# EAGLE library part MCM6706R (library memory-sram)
MEMORY
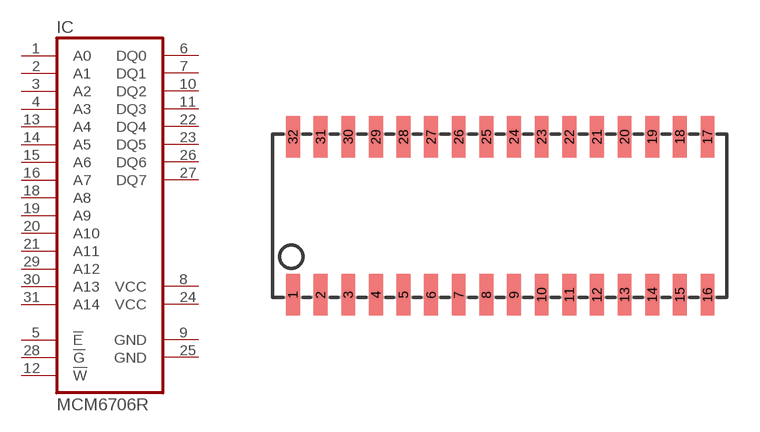
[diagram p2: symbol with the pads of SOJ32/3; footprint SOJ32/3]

Designator prefix IC

## MCM6706R  [SOJ32/3]
1  A0  in
2  A1  in
3  A2  in
4  A3  in
5  !E  in
6  DQ0
7  DQ1
8  VCC  pwr
9  GND  pwr
10  DQ2
11  DQ3
12  !W  in
13  A4  in
14  A5  in
15  A6  in
16  A7  in
18  A8  in
19  A9  in
20  A10  in
21  A11  in
22  DQ4
23  DQ5
24  VCC  pwr
25  GND  pwr
26  DQ6
27  DQ7
28  !G  in
29  A12  in
30  A13  in
31  A14  in

## Footprint SOJ32/3 (pad centres in mm)
Small Outline J-Bend
smd 0.635 x 1.905: 1 -9.525,-3.632; 2 -8.255,-3.632; 3 -6.985,-3.632; 4 -5.715,-3.632; 5 -4.445,-3.632; 6 -3.175,-3.632; 7 -1.905,-3.632; 8 -0.635,-3.632; 9 0.635,-3.632; 10 1.905,-3.632; 11 3.175,-3.632; 12 4.445,-3.632; 13 5.715,-3.632; 14 6.985,-3.632; 15 8.255,-3.632; 16 9.525,-3.632; 17 9.525,3.632; 18 8.255,3.632; 19 6.985,3.632; 20 5.715,3.632; 21 4.445,3.632; 22 3.175,3.632; 23 1.905,3.632; 24 0.635,3.632; 25 -0.635,3.632; 26 -1.905,3.632; 27 -3.175,3.632; 28 -4.445,3.632; 29 -5.715,3.632; 30 -6.985,3.632; 31 -8.255,3.632; 32 -9.525,3.632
